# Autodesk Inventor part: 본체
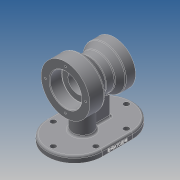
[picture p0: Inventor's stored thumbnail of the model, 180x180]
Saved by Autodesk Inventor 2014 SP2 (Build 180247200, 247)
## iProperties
Created: 2020-01
Part Number: 본체
Material: 일반
Document SubType Name: Modeling
Designer: kb542-10
Density: 1 g/cm^3
Appearance: 기본값
Mass: 347.447 g
Surface Area: 654.889 cm^2
Volume: 347.447 cm^3
Author: kb542-10
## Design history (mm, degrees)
sketch "스케치1"
  geometry: L1 (0, 0)-(0, -80); L2 (0, -80)-(35, -80); L3 (35, -80)-(35, -64); L4 (35, -64)-(27.5, -53.289); L5 (27.5, -53.289)-(27.5, -38.897); L6 (27.5, -38.897)-(40, -24); L7 (40, -24)-(40, 0); L8 (40, 0)-(0, 0); L9 (26, 0)-(26, -20); L10 (26, -20)-(16, -20); L11 (16, -20)-(16, -63); L12 (16, -63)-(20, -63); L13 (20, -63)-(20, -80)
  constraints: 26 end point, 6 parallel, 4 perpendicular, 2 point on line, 1 vertical
  dimensions: "d7" = 80 diameter of L7 L1; "d8" = 80 distance between parallel lines of L2 L8; "d9" = 40 deg angle of L6 L5; "d10" = 35 deg angle of L4 L5; "d11" = 16 distance of L2.end L3.end; "d12" = 24 distance of L6.end L7.end; "d13" = 70 diameter of L3 L1; "d14" = 55 diameter of L5 L1; "d15" = 52 diameter of L9 L1; "d16" = 40 diameter of L13 L1; "d17" = 32 diameter of L11 L1; "d18" = 17 distance between parallel lines of L2 L12; "d19" = 20 distance between parallel lines of L8 L10
revolve "회전1" sketch "스케치1" stored, may be unused: angle "d20" = 90 deg
node "작업 평면1"
sketch "스케치2"
  geometry: L1 (25.134, 0)-(-20.586, 0); L2 (0, 30)-(0, -110); L3 (45, -15)-(45, -65); L4 (-45, -65)-(-45, -15); A1 r 45 centre (0, -15) between (45, -15) and (-45, -15); A2 r 45 centre (0, -65) between (-45, -65) and (45, -65); 2 further points
  constraints: 10 end point, 6 point on circle, 4 tangent, 3 point on line, 2 centre point, 2 vertical alignment, 1 horizontal, 1 midpoint, 1 parallel
  dimensions: "d23" = 50 distance of A2.centre A1.centre; "d24" = 45 radius of A1; "d25" = 30 distance of point (0, 0) L2.start
extrude "돌출1" join sketch "스케치2" distance "d26" = 10; taper "d27" = 0 deg
sketch "스케치4"
  geometry: L1 (-45, 65)-(-45, 15) reference; L2 (45, 15)-(45, 65) reference; L3 (-35, 15)-(-35, 65); L4 (35, 65)-(35, 15); C1 r 4.5 at (-35, 15); C2 r 4.5 at (-35, 65); C3 r 4.5 at (0, -20); C4 r 4.5 at (35, 15); C5 r 4.5 at (35, 65); C6 r 4.5 at (0, 100); A1 r 45 centre (0, 15) between (-45, 15) and (45, 15) reference; A2 r 45 centre (0, 65) between (45, 65) and (-45, 65) reference; A3 r 35 centre (0, 65) between (35, 65) and (-35, 65); A4 r 35 centre (0, 15) between (-35, 15) and (35, 15); 1 further point
  constraints: 8 centre point, 6 point on circle, 4 coincident, 4 end point, 3 other
  dimensions: "d31" = 10 distance between parallel lines of L2 L4; "d32" = 9 diameter of C1; "d33" = 9 diameter of C3; "d34" = 9 diameter of C2; "d35" = 9 diameter of C6; "d36" = 9 diameter of C5; "d37" = 9 diameter of C4
extrude "돌출2" cut sketch "스케치4" stored distance "d38" = 10; taper "d39" = 0 deg
sketch "스케치5"
  geometry: L1 (5, 43.199)-(-5, 43.199); L2 (-5, 43.199)-(-5, 70); L3 (-5, 70)-(5, 70); L4 (5, 70)-(5, 43.199); L5 (0, 70)-(0, 74.923); L6 (0, -30)-(0, -40.513); A1 r 45 centre (0, 15) between (-45, 15) and (45, 15) reference; A2 r 16 centre (0, 28) between (5, 43.199) and (-5, 43.199); 1 further point
  constraints: 12 end point, 3 parallel, 3 point on circle, 1 centre point, 1 collinear, 1 horizontal, 1 midpoint, 1 perpendicular, 1 vertical alignment
  dimensions: "d40" = 10 distance between parallel lines of L2 L4; "d41" = 32 diameter of A2; "d42" = 58 distance of A2.centre L6.start; "d43" = 100 distance of L5.start L6.start
extrude "돌출3" join sketch "스케치5" stored distance "d44" = 10; taper "d45" = 0 deg
sketch "스케치6" dims "d46" = 66
  geometry: C1 r 26 at (0, 0) reference; C2 r 40 at (0, 0) reference; 5 further points
  constraints: 2 vertical alignment, 1 coincident, 7 other
  dimensions: "d49" = 360 deg dimension on C1.centre point (0, 33) (derived)
hole "구멍1" sketch "스케치6" at (0, 33), (-33, 0), (0, -33), (33, 0) diameter "d51" = 3.242; stored, may be unused: countersink angle "d55" = 90 deg, drill point angle "d57" = 118 deg; dims "d52" = 9, "d53" = 4, "d54" = 2, "d56" = 11
sketch "스케치7" dims "d58" = 55
  geometry: C1 r 20 at (0, 0) reference; A1 r 35 centre (0, 0) between (-5, -34.641) and (5, -34.641) reference; 5 further points
  constraints: 2 vertical alignment, 1 coincident, 7 other
  dimensions: "d61" = 360 deg dimension on A1.centre point (0, 27.5) (derived)
hole "구멍2" sketch "스케치7" at (0, 27.5), (-27.5, 0), (0, -27.5), (27.5, 0) diameter "d63" = 3.242; stored, may be unused: countersink angle "d67" = 90 deg, drill point angle "d69" = 118 deg; dims "d64" = 9, "d65" = 4, "d66" = 2, "d68" = 11
chamfer "모따기1" distance "d70" = 1; stored, may be unused: second distance "d71" = 2, angle "d72" = 45 deg
chamfer "모따기2" distance "d73" = 1; stored, may be unused: second distance "d74" = 2, angle "d75" = 45 deg
fillet "모깎기1" dims "d76" = 3, "d77" = 0.3
sketch "스케치8"
  geometry: L1 (50, 0)-(95, 0) reference; L2 (0, 7)-(0, 7) reference; L3 (0, 0)-(0, 7) reference; L4 (0, 0)-(0, 0) reference; L5 (0, 0)-(0, 7) reference; L6 (-45, 0)-(-45, 7) reference; 2 further points
  constraints: 1 other
  dimensions: "d78" = 4 distance from line of L1 point (25, 4); "d79" = 70 distance from line of point (25, 4) L6
feature "엠보싱1" sketch "스케치8" dims "d7" = 80, "d8" = 80, "d9" = 40 deg, "d10" = 35 deg, "d11" = 16, "d12" = 24, "d13" = 70, "d14" = 55, "d15" = 52, "d16" = 40, "d17" = 32, "d18" = 17, "d19" = 20, "d23" = 50, "d24" = 45, "d25" = 30, "d80" = 0.5, "d81" = 0
node "솔리드1"
node "투영된 루프1"
